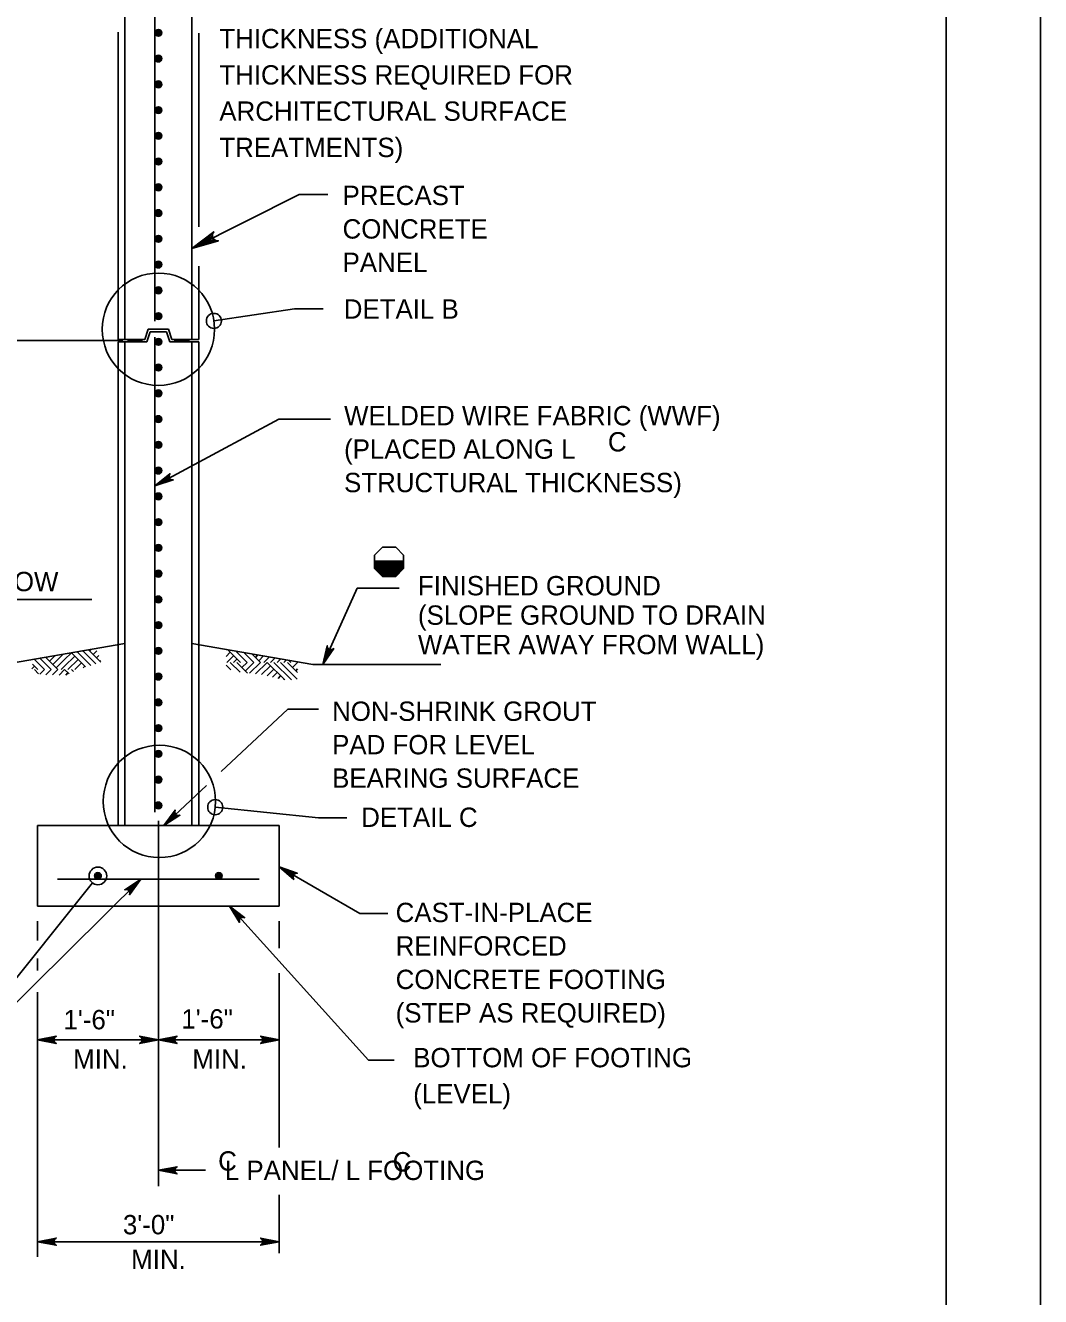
# Model space of a CAD drawing. Extents: x 3385 to 6532, y -616 to 1166.
# Drawn here: x 6123.1 to 6284.3, y 859.8 to 1061.6 of the extents above; entities that cross this region are included whole.
import ezdxf

# ---------------------------------------------------------------- set-up
doc = ezdxf.new("R2010")
doc.units = 0
for name, color, linetype in [('1', 7, 'Continuous'), ('2', 7, 'Continuous'), ('PLT-BNDY', 7, 'Continuous')]:
    doc.layers.add(name, color=color, linetype=linetype)

msp = doc.modelspace()

# ---------------------------------------------------------------- linework, layer by layer
at = {"layer": '1'}
for p, q in [((6138.91, 1088.17), (6138.91, 1011.77)), ((6149.58, 1088.17), (6149.58, 1011.77)), ((6143.71, 1086.04), (6143.71, 1014.68)), ((6137.85, 1060.56), (6137.85, 1011.77)), ((6150.65, 1060.4), (6150.65, 1029.62)), ((6160.02, 1051.67), (6160.02, 1051.67)), ((6166.61, 1034.79), (6149.58, 1026.2)), ((6166.61, 1034.79), (6171.15, 1034.79)), ((6150.65, 1023.39), (6150.65, 1011.77)), ((6153.07, 1014.7), (6165.88, 1016.63)), ((6165.88, 1016.63), (6170.42, 1016.63)), ((6142.65, 1013.37), (6142.11, 1011.77)), ((6145.85, 1013.37), (6142.65, 1013.37)), ((6145.85, 1013.37), (6146.38, 1011.77)), ((6138.62, 1011.57), (6101.49, 1011.57)), ((6138.91, 1011.77), (6137.85, 1011.77)), ((6138.91, 1011.37), (6137.85, 1011.37)), ((6137.85, 1011.37), (6137.85, 934.57)), ((6142.11, 1011.77), (6138.91, 1011.77)), ((6142.4, 1011.37), (6138.91, 1011.37)), ((6138.91, 1011.37), (6138.91, 934.57)), ((6139.43, 1011.77), (6139.43, 1011.37)), ((6139.43, 1011.6), (6139.6, 1011.77)), ((6139.43, 1011.38), (6139.83, 1011.77)), ((6139.65, 1011.37), (6140.05, 1011.77)), ((6139.88, 1011.37), (6140.28, 1011.77)), ((6140.1, 1011.37), (6140.5, 1011.77)), ((6140.33, 1011.37), (6140.7, 1011.74)), ((6140.56, 1011.37), (6140.7, 1011.52)), ((6140.7, 1011.74), (6140.73, 1011.77)), ((6140.7, 1011.52), (6140.96, 1011.77)), ((6140.78, 1011.37), (6141.18, 1011.77)), ((6141.01, 1011.37), (6141.41, 1011.77)), ((6141.24, 1011.37), (6141.6, 1011.74)), ((6141.46, 1011.37), (6141.6, 1011.51)), ((6141.6, 1011.77), (6141.6, 1011.37)), ((6142.94, 1012.97), (6142.4, 1011.37)), ((6145.56, 1012.97), (6142.94, 1012.97)), ((6143.71, 1012.13), (6143.71, 936.71)), ((6145.56, 1012.97), (6146.09, 1011.37)), ((6149.58, 1011.37), (6146.09, 1011.37)), ((6149.58, 1011.77), (6146.38, 1011.77)), ((6146.89, 1011.77), (6146.89, 1011.37)), ((6146.89, 1011.6), (6147.07, 1011.77)), ((6146.89, 1011.38), (6147.29, 1011.77)), ((6147.12, 1011.37), (6147.52, 1011.77)), ((6147.35, 1011.37), (6147.75, 1011.77)), ((6147.57, 1011.37), (6147.97, 1011.77)), ((6147.8, 1011.37), (6148.17, 1011.74)), ((6148.02, 1011.37), (6148.17, 1011.52)), ((6148.17, 1011.74), (6148.2, 1011.77)), ((6148.17, 1011.52), (6148.43, 1011.77)), ((6148.25, 1011.37), (6148.65, 1011.77)), ((6148.48, 1011.37), (6148.88, 1011.77)), ((6148.7, 1011.37), (6149.07, 1011.74)), ((6148.93, 1011.37), (6149.07, 1011.51)), ((6149.07, 1011.77), (6149.07, 1011.37)), ((6149.58, 1011.77), (6150.65, 1011.77)), ((6149.58, 1011.37), (6149.58, 934.57)), ((6149.58, 1011.37), (6150.65, 1011.37)), ((6150.65, 1011.37), (6150.65, 934.57)), ((6163.38, 999.1), (6143.71, 988.52)), ((6163.38, 999.1), (6171.59, 999.1)), ((6179.83, 978.76), (6178.58, 977.51)), ((6178.58, 977.51), (6178.58, 975.39)), ((6179.83, 978.76), (6181.95, 978.76)), ((6181.95, 978.76), (6183.2, 977.51)), ((6183.2, 977.51), (6183.2, 975.39)), ((6178.57, 976.57), (6183.19, 976.57)), ((6178.57, 975.47), (6183.19, 975.47)), ((6178.58, 975.97), (6183.19, 975.97)), ((6178.58, 975.87), (6183.19, 975.87)), ((6178.58, 975.77), (6183.19, 975.77)), ((6178.58, 975.67), (6183.19, 975.67)), ((6178.58, 975.57), (6183.19, 975.57)), ((6179.83, 974.14), (6178.58, 975.39)), ((6178.59, 976.47), (6183.19, 976.47)), ((6178.59, 976.37), (6183.19, 976.37)), ((6178.59, 976.27), (6183.19, 976.27)), ((6178.59, 976.17), (6183.19, 976.17)), ((6178.59, 976.07), (6183.19, 976.07)), ((6178.59, 975.37), (6183.15, 975.37)), ((6178.69, 975.27), (6183.05, 975.27)), ((6178.8, 975.17), (6182.96, 975.17)), ((6178.9, 975.07), (6182.86, 975.07)), ((6179, 974.97), (6182.76, 974.97)), ((6179.1, 974.87), (6182.67, 974.87)), ((6181.68, 976.57), (6183.19, 976.57)), ((6181.95, 974.14), (6183.2, 975.39)), ((6179.2, 974.77), (6182.57, 974.77)), ((6179.31, 974.67), (6182.47, 974.67)), ((6179.41, 974.57), (6182.38, 974.57)), ((6179.51, 974.47), (6182.28, 974.47)), ((6179.61, 974.37), (6182.19, 974.37)), ((6179.71, 974.27), (6182.09, 974.27)), ((6179.82, 974.17), (6181.99, 974.17)), ((6179.83, 974.14), (6181.95, 974.14)), ((6175.8, 972.28), (6170.37, 960.17)), ((6175.8, 972.28), (6182.49, 972.28)), ((6119.71, 960.17), (6138.91, 963.48)), ((6149.58, 963.48), (6168.78, 960.17)), ((6126.16, 959.35), (6124.51, 961)), ((6127.23, 959.35), (6125.42, 961.16)), ((6128.3, 959.35), (6126.33, 961.31)), ((6126.43, 961.22), (6126.56, 961.35)), ((6126.96, 960.69), (6127.85, 961.57)), ((6127.5, 960.15), (6129.14, 961.8)), ((6128.03, 959.62), (6129.36, 960.95)), ((6129.36, 960.95), (6130.43, 962.02)), ((6129.36, 959.89), (6130.96, 961.49)), ((6129.9, 959.35), (6131.5, 960.95)), ((6132.7, 959.75), (6130.43, 962.02)), ((6133.5, 960.01), (6131.34, 962.17)), ((6134.31, 960.27), (6132.25, 962.33)), ((6135.11, 960.53), (6133.16, 962.49)), ((6133.36, 962.29), (6133.65, 962.57)), ((6133.9, 961.75), (6134.46, 962.31)), ((6134.43, 961.22), (6134.77, 961.56)), ((6134.96, 960.69), (6135.08, 960.8)), ((6155.03, 962.51), (6155.06, 962.54)), ((6155.03, 961.44), (6155.67, 962.08)), ((6155.13, 960.48), (6156.2, 961.54)), ((6157.27, 960.48), (6155.24, 962.51)), ((6156.2, 960.48), (6156.73, 961.01)), ((6158.33, 960.48), (6156.53, 962.28)), ((6159.4, 960.48), (6157.81, 962.06)), ((6160.47, 960.48), (6159.1, 961.84)), ((6159.13, 961.81), (6159.15, 961.83)), ((6159.67, 961.28), (6160.06, 961.67)), ((6160.2, 960.74), (6160.97, 961.52)), ((6161, 960.48), (6161.88, 961.36)), ((6162.07, 960.48), (6162.79, 961.2)), ((6163.13, 960.48), (6163.7, 961.05)), ((6164.2, 960.48), (6164.61, 960.89)), ((6165.27, 960.48), (6164.9, 960.84)), ((6124.15, 959.47), (6124.56, 959.89)), ((6125.1, 959.35), (6124.24, 960.21)), ((6125.23, 958.68), (6124.56, 959.35)), ((6125.44, 958.63), (6126.16, 959.35)), ((6126.37, 958.5), (6127.23, 959.35)), ((6127.42, 958.48), (6128.3, 959.35)), ((6128.48, 958.47), (6129.36, 959.35)), ((6128.83, 959.35), (6129.36, 959.89)), ((6130.08, 958.64), (6129.36, 959.35)), ((6129.53, 958.45), (6129.9, 958.82)), ((6130.75, 959.03), (6130.43, 959.35)), ((6130.96, 959.35), (6132.03, 960.42)), ((6132.3, 959.62), (6132.56, 959.89)), ((6155.78, 959.29), (6155.03, 960.05)), ((6157.22, 958.92), (6155.67, 960.48)), ((6158.42, 958.78), (6156.73, 960.48)), ((6157.53, 959.68), (6158.33, 960.48)), ((6158.07, 959.14), (6159.4, 960.48)), ((6158.74, 958.75), (6160.47, 960.48)), ((6159.69, 958.64), (6161.53, 960.48)), ((6160.65, 958.53), (6162.07, 959.94)), ((6164.31, 957.7), (6161.53, 960.48)), ((6161.53, 958.34), (6162.6, 959.41)), ((6162.4, 958.14), (6163.13, 958.88)), ((6165.37, 957.71), (6162.6, 960.48)), ((6166.31, 957.83), (6163.67, 960.48)), ((6166.34, 958.87), (6164.73, 960.48)), ((6165.53, 959.68), (6166.33, 960.48)), ((6166.07, 959.14), (6166.36, 959.44)), ((6166.33, 960.48), (6166.19, 960.62)), ((6189.11, 960.17), (6168.78, 960.17)), ((6163.26, 957.94), (6163.67, 958.34)), ((6164.13, 957.74), (6164.2, 957.81)), ((6164.82, 953.06), (6154.24, 943.14)), ((6164.82, 953.06), (6169.68, 953.06)), ((6151.88, 940.92), (6145.11, 934.57)), ((6153.28, 937.49), (6169.66, 935.8)), ((6125.05, 934.57), (6125.05, 921.77)), ((6138.91, 934.57), (6125.05, 934.57)), ((6149.58, 934.57), (6138.91, 934.57)), ((6144.25, 935.31), (6144.25, 877.31)), ((6163.45, 934.57), (6149.58, 934.57)), ((6163.45, 934.57), (6163.45, 921.77)), ((6169.66, 935.8), (6174.2, 935.8)), ((6176.23, 920.63), (6163.45, 928)), ((6106.7, 891.67), (6141.46, 926.04)), ((6133.77, 925.48), (6106.7, 891.67)), ((6160.25, 926.04), (6128.25, 926.04)), ((6163.45, 921.77), (6125.05, 921.77)), ((6155.55, 921.77), (6177.63, 897.33)), ((6176.23, 920.63), (6180.7, 920.63)), ((6125.05, 919.37), (6125.05, 916.31)), ((6163.45, 919.37), (6163.45, 915.13)), ((6125.05, 913.48), (6125.05, 911.58)), ((6163.45, 911.13), (6163.45, 883.47)), ((6125.05, 908.1), (6125.05, 866.09)), ((6125.05, 900.55), (6163.45, 900.55)), ((6177.63, 897.33), (6181.67, 897.33)), ((6144.25, 877.31), (6144.25, 883.23)), ((6144.25, 879.83), (6151.71, 879.83)), ((6163.45, 875.95), (6163.45, 866.7)), ((6125.05, 868.5), (6163.45, 868.5))]:
    msp.add_line(p, q, dxfattribs=at)
for points in [[(6149.58, 1026.2), (6153.05, 1028.86), (6152.86, 1028.5), (6152.84, 1028.17), (6152.92, 1027.89), (6153.1, 1027.65), (6153.38, 1027.47), (6153.78, 1027.42), (6149.58, 1026.2), (6153.38, 1027.47), (6153.1, 1027.65), (6149.58, 1026.2), (6152.92, 1027.89), (6152.84, 1028.17), (6149.58, 1026.2), (6152.86, 1028.5)], [(6143.71, 988.52), (6146.08, 990.42), (6145.95, 990.17), (6145.94, 989.94), (6146, 989.75), (6146.13, 989.59), (6146.33, 989.47), (6146.61, 989.44), (6143.71, 988.52), (6146.33, 989.47), (6146.13, 989.59), (6143.71, 988.52), (6146, 989.75), (6145.94, 989.94), (6143.71, 988.52), (6145.95, 990.17)], [(6093.38, 921.77), (6086.22, 970.48), (6133.69, 970.48)], [(6170.37, 960.17), (6171.08, 963.12), (6171.13, 962.85), (6171.27, 962.66), (6171.43, 962.55), (6171.63, 962.5), (6171.86, 962.52), (6172.1, 962.67), (6170.37, 960.17), (6171.86, 962.52), (6171.63, 962.5), (6170.37, 960.17), (6171.43, 962.55), (6171.27, 962.66), (6170.37, 960.17), (6171.13, 962.85)], [(6145.11, 934.57), (6146.9, 937.02), (6146.85, 936.75), (6146.9, 936.52), (6147.01, 936.35), (6147.17, 936.23), (6147.39, 936.16), (6147.67, 936.21), (6145.11, 934.57), (6147.39, 936.16), (6147.17, 936.23), (6145.11, 934.57), (6147.01, 936.35), (6146.9, 936.52), (6145.11, 934.57), (6146.85, 936.75)], [(6163.45, 928), (6166.31, 927), (6166.03, 926.97), (6165.83, 926.86), (6165.7, 926.7), (6165.63, 926.51), (6165.63, 926.28), (6165.75, 926.03), (6163.45, 928), (6165.63, 926.28), (6165.63, 926.51), (6163.45, 928), (6165.7, 926.7), (6165.83, 926.86), (6163.45, 928), (6166.03, 926.97)], [(6141.46, 926.04), (6139.68, 923.58), (6139.74, 923.85), (6139.69, 924.08), (6139.58, 924.25), (6139.41, 924.37), (6139.19, 924.43), (6138.91, 924.39), (6141.46, 926.04), (6139.19, 924.43), (6139.41, 924.37), (6141.46, 926.04), (6139.58, 924.25), (6139.69, 924.08), (6141.46, 926.04), (6139.74, 923.85)], [(6155.55, 921.77), (6157.96, 919.93), (6157.82, 919.97), (6157.69, 920), (6157.57, 919.98), (6157.46, 919.95), (6157.37, 919.9), (6157.29, 919.84), (6157.23, 919.76), (6157.16, 919.68), (6157.13, 919.57), (6157.09, 919.46), (6157.11, 919.32), (6157.13, 919.18), (6155.55, 921.77), (6157.11, 919.32), (6157.09, 919.46), (6155.55, 921.77), (6157.13, 919.57), (6157.16, 919.68), (6155.55, 921.77), (6157.23, 919.76), (6157.29, 919.84), (6155.55, 921.77), (6157.37, 919.9), (6157.46, 919.95), (6155.55, 921.77), (6157.57, 919.98), (6157.69, 920), (6155.55, 921.77), (6157.82, 919.97)], [(6125.05, 900.55), (6128.03, 901.11), (6127.8, 900.95), (6127.68, 900.75), (6127.65, 900.55), (6127.68, 900.35), (6127.8, 900.15), (6128.03, 899.99), (6125.05, 900.55), (6127.8, 900.15), (6127.68, 900.35), (6125.05, 900.55), (6127.65, 900.55), (6127.68, 900.75), (6125.05, 900.55), (6127.8, 900.95)], [(6144.25, 900.55), (6141.27, 899.99), (6141.5, 900.15), (6141.61, 900.35), (6141.65, 900.55), (6141.61, 900.75), (6141.5, 900.95), (6141.27, 901.11), (6144.25, 900.55), (6141.5, 900.95), (6141.61, 900.75), (6144.25, 900.55), (6141.65, 900.55), (6141.61, 900.35), (6144.25, 900.55), (6141.5, 900.15)], [(6144.25, 900.55), (6147.23, 899.99), (6147, 900.15), (6146.88, 900.35), (6146.85, 900.55), (6146.88, 900.75), (6147, 900.95), (6147.23, 901.11), (6144.25, 900.55), (6147, 900.95), (6146.88, 900.75), (6144.25, 900.55), (6146.85, 900.55), (6146.88, 900.35), (6144.25, 900.55), (6147, 900.15)], [(6163.45, 900.55), (6160.47, 899.99), (6160.7, 900.15), (6160.81, 900.35), (6160.85, 900.55), (6160.81, 900.75), (6160.7, 900.95), (6160.47, 901.11), (6163.45, 900.55), (6160.7, 900.95), (6160.81, 900.75), (6163.45, 900.55), (6160.85, 900.55), (6160.81, 900.35), (6163.45, 900.55), (6160.7, 900.15)], [(6144.25, 879.83), (6147.23, 880.39), (6147, 880.23), (6146.88, 880.03), (6146.85, 879.83), (6146.88, 879.63), (6147, 879.43), (6147.23, 879.27), (6144.25, 879.83), (6147, 879.43), (6146.88, 879.63), (6144.25, 879.83), (6146.85, 879.83), (6146.88, 880.03), (6144.25, 879.83), (6147, 880.23)], [(6125.05, 868.5), (6128.03, 869.06), (6127.8, 868.9), (6127.68, 868.7), (6127.65, 868.5), (6127.68, 868.3), (6127.8, 868.1), (6128.03, 867.94), (6125.05, 868.5), (6127.8, 868.1), (6127.68, 868.3), (6125.05, 868.5), (6127.65, 868.5), (6127.68, 868.7), (6125.05, 868.5), (6127.8, 868.9)], [(6163.45, 868.5), (6160.47, 867.94), (6160.7, 868.1), (6160.81, 868.3), (6160.85, 868.5), (6160.81, 868.7), (6160.7, 868.9), (6160.47, 869.06), (6163.45, 868.5), (6160.7, 868.9), (6160.81, 868.7), (6163.45, 868.5), (6160.85, 868.5), (6160.81, 868.3), (6163.45, 868.5), (6160.7, 868.1)]]:
    msp.add_lwpolyline(points, dxfattribs=at)
for centre, radius in [((6144.25, 1060.44), 0.533), ((6144.25, 1060.44), 0.4), ((6144.25, 1060.44), 0.267), ((6144.25, 1060.44), 0.133), ((6144.25, 1056.35), 0.533), ((6144.25, 1056.35), 0.4), ((6144.25, 1056.35), 0.267), ((6144.25, 1056.35), 0.133), ((6144.25, 1052.26), 0.533), ((6144.25, 1052.26), 0.4), ((6144.25, 1052.26), 0.267), ((6144.25, 1052.26), 0.133), ((6144.25, 1048.17), 0.533), ((6144.25, 1048.17), 0.4), ((6144.25, 1048.17), 0.267), ((6144.25, 1048.17), 0.133), ((6144.25, 1044.09), 0.533), ((6144.25, 1044.09), 0.4), ((6144.25, 1044.09), 0.267), ((6144.25, 1044.09), 0.133), ((6144.25, 1040), 0.533), ((6144.25, 1040), 0.4), ((6144.25, 1040), 0.267), ((6144.25, 1040), 0.133), ((6144.25, 1035.91), 0.533), ((6144.25, 1035.91), 0.4), ((6144.25, 1035.91), 0.267), ((6144.25, 1035.91), 0.133), ((6144.25, 1031.82), 0.533), ((6144.25, 1031.82), 0.4), ((6144.25, 1031.82), 0.267), ((6144.25, 1031.82), 0.133), ((6144.25, 1027.73), 0.533), ((6144.25, 1027.73), 0.4), ((6144.25, 1027.73), 0.267), ((6144.25, 1027.73), 0.133), ((6144.25, 1023.64), 0.533), ((6144.25, 1023.64), 0.4), ((6144.25, 1023.64), 0.267), ((6144.25, 1023.64), 0.133), ((6144.25, 1013.37), 8.92), ((6144.25, 1019.55), 0.533), ((6144.25, 1019.55), 0.4), ((6144.25, 1019.55), 0.267), ((6144.25, 1019.55), 0.133), ((6144.25, 1015.46), 0.533), ((6144.25, 1015.46), 0.4), ((6144.25, 1015.46), 0.267), ((6144.25, 1015.46), 0.133), ((6153.07, 1014.7), 1.2), ((6144.25, 1011.37), 0.533), ((6144.25, 1011.37), 0.4), ((6144.25, 1011.37), 0.267), ((6144.25, 1011.37), 0.133), ((6144.25, 1007.29), 0.533), ((6144.25, 1007.29), 0.4), ((6144.25, 1007.29), 0.267), ((6144.25, 1007.29), 0.133), ((6144.25, 1003.2), 0.533), ((6144.25, 1003.2), 0.4), ((6144.25, 1003.2), 0.267), ((6144.25, 1003.2), 0.133), ((6144.25, 999.11), 0.533), ((6144.25, 999.11), 0.4), ((6144.25, 999.11), 0.267), ((6144.25, 999.11), 0.133), ((6144.25, 995.02), 0.533), ((6144.25, 995.02), 0.4), ((6144.25, 995.02), 0.267), ((6144.25, 995.02), 0.133), ((6144.25, 990.93), 0.533), ((6144.25, 990.93), 0.4), ((6144.25, 990.93), 0.267), ((6144.25, 990.93), 0.133), ((6144.25, 986.84), 0.533), ((6144.25, 986.84), 0.4), ((6144.25, 986.84), 0.267), ((6144.25, 986.84), 0.133), ((6144.25, 982.75), 0.533), ((6144.25, 982.75), 0.4), ((6144.25, 982.75), 0.267), ((6144.25, 982.75), 0.133), ((6144.25, 978.66), 0.533), ((6144.25, 978.66), 0.4), ((6144.25, 978.66), 0.267), ((6144.25, 978.66), 0.133), ((6144.25, 974.57), 0.533), ((6144.25, 974.57), 0.4), ((6144.25, 974.57), 0.267), ((6144.25, 974.57), 0.133), ((6144.25, 970.48), 0.533), ((6144.25, 970.48), 0.4), ((6144.25, 970.48), 0.267), ((6144.25, 970.48), 0.133), ((6144.25, 966.4), 0.533), ((6144.25, 966.4), 0.4), ((6144.25, 966.4), 0.267), ((6144.25, 966.4), 0.133), ((6144.25, 962.31), 0.533), ((6144.25, 962.31), 0.4), ((6144.25, 962.31), 0.267), ((6144.25, 962.31), 0.133), ((6144.25, 958.22), 0.533), ((6144.25, 958.22), 0.4), ((6144.25, 958.22), 0.267), ((6144.25, 958.22), 0.133), ((6144.25, 954.13), 0.533), ((6144.25, 954.13), 0.4), ((6144.25, 954.13), 0.267), ((6144.25, 954.13), 0.133), ((6144.25, 950.04), 0.533), ((6144.25, 950.04), 0.4), ((6144.25, 950.04), 0.267), ((6144.25, 950.04), 0.133), ((6144.41, 938.41), 8.92), ((6144.25, 945.95), 0.533), ((6144.25, 945.95), 0.4), ((6144.25, 945.95), 0.267), ((6144.25, 945.95), 0.133), ((6144.25, 941.86), 0.533), ((6144.25, 941.86), 0.4), ((6144.25, 941.86), 0.267), ((6144.25, 941.86), 0.133), ((6153.28, 937.49), 1.2), ((6144.25, 937.77), 0.533), ((6144.25, 937.77), 0.4), ((6144.25, 937.77), 0.267), ((6144.25, 937.77), 0.133), ((6134.65, 926.57), 1.4), ((6134.65, 926.57), 0.533), ((6134.65, 926.57), 0.4), ((6134.65, 926.57), 0.267), ((6134.65, 926.57), 0.133), ((6153.85, 926.57), 0.533), ((6153.85, 926.57), 0.4), ((6153.85, 926.57), 0.267), ((6153.85, 926.57), 0.133)]:
    msp.add_circle(centre, radius, dxfattribs=at)
at = {"layer": '2'}
msp.add_line((6269.34, 1150.69), (6269.34, 586.69), dxfattribs=at)
at = {"layer": 'PLT-BNDY'}
msp.add_lwpolyline([(5443.34, 1165.69), (6284.34, 1165.69), (6284.34, 571.69), (5443.34, 571.69)], close=True, dxfattribs=at)

# ---------------------------------------------------------------- texts
at = {"layer": '1'}
for s, height, p in [('THICKNESS (ADDITIONAL ', 3.072, (6153.93, 1057.99)), ('THICKNESS REQUIRED FOR', 3.072, (6153.93, 1052.23)), ('ARCHITECTURAL SURFACE ', 3.072, (6153.93, 1046.47)), ('TREATMENTS)', 3.072, (6153.93, 1040.71)), ('PRECAST ', 3.072, (6173.5, 1033.09)), ('CONCRETE', 3.072, (6173.5, 1027.77)), ('PANEL', 3.072, (6173.5, 1022.46)), ('DETAIL B', 3.072, (6173.69, 1015.05)), ('WELDED WIRE FABRIC (WWF)', 3.0721, (6173.74, 998.12)), ('C', 3.07, (6215.64, 993.97)), ('(PLACED ALONG L', 3.0721, (6173.74, 992.81)), ('STRUCTURAL THICKNESS)', 3.0721, (6173.74, 987.5)), ('ELEVATION BELOW', 3.0721, (6089.34, 971.78)), ('FINISHED GROUND', 3.0721, (6185.47, 971.12)), ('(SLOPE GROUND TO DRAIN', 3.0721, (6185.47, 966.45)), ('WATER AWAY FROM WALL)', 3.0721, (6185.47, 961.78)), ('NON-SHRINK GROUT', 3.0721, (6171.84, 951.19)), ('PAD FOR LEVEL ', 3.0721, (6171.84, 945.88)), ('BEARING SURFACE ', 3.0721, (6171.84, 940.57)), ('DETAIL C', 3.072, (6176.46, 934.35)), ('CAST-IN-PLACE', 3.0721, (6181.93, 919.24)), ('REINFORCED', 3.072, (6181.93, 913.93)), ('CONCRETE FOOTING', 3.0721, (6181.93, 908.61)), ('(STEP AS REQUIRED)', 3.0721, (6181.93, 903.3)), ('1\'-6"', 3.072, (6129.18, 902.22)), ('1\'-6"', 3.072, (6147.9, 902.34)), ('MIN.', 3.072, (6130.72, 895.97)), ('MIN.', 3.072, (6149.64, 895.97)), ('BOTTOM OF FOOTING', 3.0721, (6184.72, 896.19)), ('(LEVEL)', 3.072, (6184.72, 890.45)), ('C', 3.07, (6153.74, 879.78)), ('C', 3.07, (6181.46, 879.66)), ('L PANEL/ L FOOTING', 3.0721, (6154.81, 878.29)), ('3\'-0"', 3.072, (6138.62, 869.67)), ('MIN.', 3.072, (6139.94, 864.15))]:
    msp.add_text(s, height=height, dxfattribs=at).set_placement(p)

doc.saveas('drawing.dxf')
